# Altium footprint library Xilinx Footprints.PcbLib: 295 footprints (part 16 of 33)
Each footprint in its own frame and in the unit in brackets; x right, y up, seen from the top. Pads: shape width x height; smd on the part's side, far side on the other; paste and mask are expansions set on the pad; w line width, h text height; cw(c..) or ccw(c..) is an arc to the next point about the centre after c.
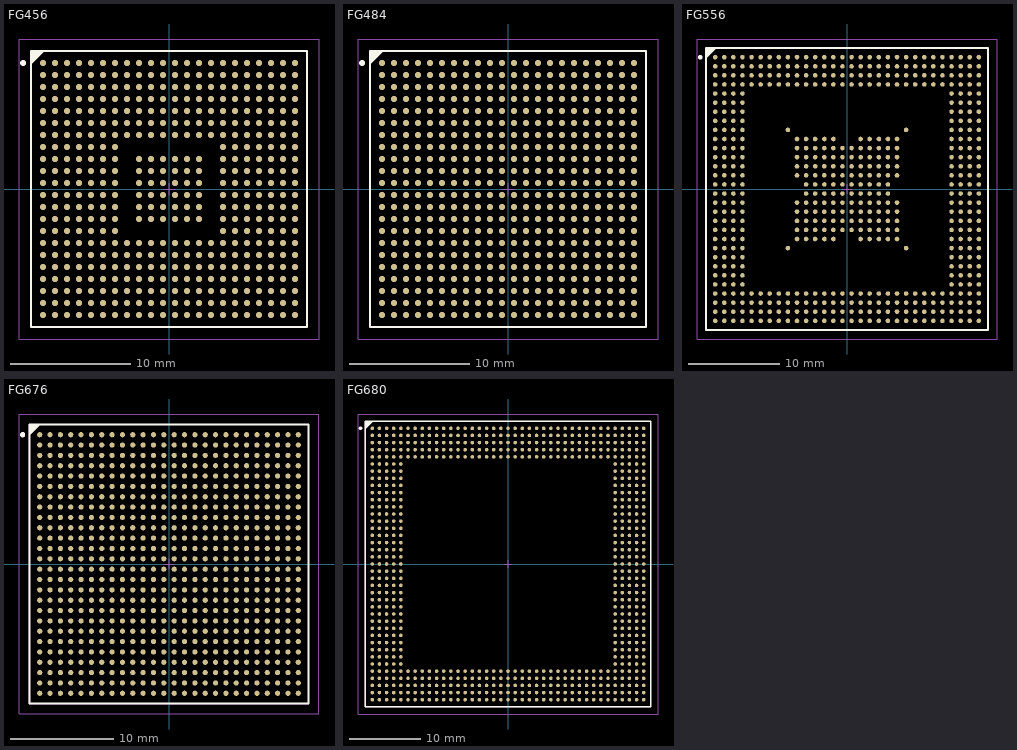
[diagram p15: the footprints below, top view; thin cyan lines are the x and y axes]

## FG456 [mm] "456-Ball Fine Pitch Ball Grid Array (FG456)"
height 2.6
pads (456):
  round 0.5 smd: A1(-10.5,10.5) A2(-9.5,10.5) A3(-8.5,10.5) A4(-7.5,10.5) A5(-6.5,10.5) A6(-5.5,10.5) A7(-4.5,10.5) A8(-3.5,10.5) A9(-2.5,10.5) A10(-1.5,10.5) A11(-0.5,10.5) A12(0.5,10.5) A13(1.5,10.5) A14(2.5,10.5) A15(3.5,10.5) A16(4.5,10.5) A17(5.5,10.5) A18(6.5,10.5) A19(7.5,10.5) A20(8.5,10.5) A21(9.5,10.5) A22(10.5,10.5) AA1(-10.5,-9.5) AA2(-9.5,-9.5) AA3(-8.5,-9.5) AA4(-7.5,-9.5) AA5(-6.5,-9.5) AA6(-5.5,-9.5) AA7(-4.5,-9.5) AA8(-3.5,-9.5) AA9(-2.5,-9.5) AA10(-1.5,-9.5) AA11(-0.5,-9.5) AA12(0.5,-9.5) AA13(1.5,-9.5) AA14(2.5,-9.5) AA15(3.5,-9.5) AA16(4.5,-9.5) AA17(5.5,-9.5) AA18(6.5,-9.5) AA19(7.5,-9.5) AA20(8.5,-9.5) AA21(9.5,-9.5) AA22(10.5,-9.5) AB1(-10.5,-10.5) AB2(-9.5,-10.5) AB3(-8.5,-10.5) AB4(-7.5,-10.5) AB5(-6.5,-10.5) AB6(-5.5,-10.5) AB7(-4.5,-10.5) AB8(-3.5,-10.5) AB9(-2.5,-10.5) AB10(-1.5,-10.5) AB11(-0.5,-10.5) AB12(0.5,-10.5) AB13(1.5,-10.5) AB14(2.5,-10.5) AB15(3.5,-10.5) AB16(4.5,-10.5) AB17(5.5,-10.5) AB18(6.5,-10.5) AB19(7.5,-10.5) AB20(8.5,-10.5) AB21(9.5,-10.5) AB22(10.5,-10.5) B1(-10.5,9.5) B2(-9.5,9.5) B3(-8.5,9.5) B4(-7.5,9.5) B5(-6.5,9.5) B6(-5.5,9.5) B7(-4.5,9.5) B8(-3.5,9.5) B9(-2.5,9.5) B10(-1.5,9.5) B11(-0.5,9.5) B12(0.5,9.5) B13(1.5,9.5) B14(2.5,9.5) B15(3.5,9.5) B16(4.5,9.5) B17(5.5,9.5) B18(6.5,9.5) B19(7.5,9.5) B20(8.5,9.5) B21(9.5,9.5) B22(10.5,9.5) C1(-10.5,8.5) C2(-9.5,8.5) C3(-8.5,8.5) C4(-7.5,8.5) C5(-6.5,8.5) C6(-5.5,8.5) C7(-4.5,8.5) C8(-3.5,8.5) C9(-2.5,8.5) C10(-1.5,8.5) C11(-0.5,8.5) C12(0.5,8.5) C13(1.5,8.5) C14(2.5,8.5) C15(3.5,8.5) C16(4.5,8.5) C17(5.5,8.5) C18(6.5,8.5) C19(7.5,8.5) C20(8.5,8.5) C21(9.5,8.5) C22(10.5,8.5) D1(-10.5,7.5) D2(-9.5,7.5) D3(-8.5,7.5) D4(-7.5,7.5) D5(-6.5,7.5) D6(-5.5,7.5) D7(-4.5,7.5) D8(-3.5,7.5) D9(-2.5,7.5) D10(-1.5,7.5) D11(-0.5,7.5) D12(0.5,7.5) D13(1.5,7.5) D14(2.5,7.5) D15(3.5,7.5) D16(4.5,7.5) D17(5.5,7.5) D18(6.5,7.5) D19(7.5,7.5) D20(8.5,7.5) D21(9.5,7.5) D22(10.5,7.5) E1(-10.5,6.5) E2(-9.5,6.5) E3(-8.5,6.5) E4(-7.5,6.5) E5(-6.5,6.5) E6(-5.5,6.5) E7(-4.5,6.5) E8(-3.5,6.5) E9(-2.5,6.5) E10(-1.5,6.5) E11(-0.5,6.5) E12(0.5,6.5) E13(1.5,6.5) E14(2.5,6.5) E15(3.5,6.5) E16(4.5,6.5) E17(5.5,6.5) E18(6.5,6.5) E19(7.5,6.5) E20(8.5,6.5) E21(9.5,6.5) E22(10.5,6.5) F1(-10.5,5.5) F2(-9.5,5.5) F3(-8.5,5.5) F4(-7.5,5.5) F5(-6.5,5.5) F6(-5.5,5.5) F7(-4.5,5.5) F8(-3.5,5.5) F9(-2.5,5.5) F10(-1.5,5.5) F11(-0.5,5.5) F12(0.5,5.5) F13(1.5,5.5) F14(2.5,5.5) F15(3.5,5.5) F16(4.5,5.5) F17(5.5,5.5) F18(6.5,5.5) F19(7.5,5.5) F20(8.5,5.5) F21(9.5,5.5) F22(10.5,5.5) G1(-10.5,4.5) G2(-9.5,4.5) G3(-8.5,4.5) G4(-7.5,4.5) G5(-6.5,4.5) G6(-5.5,4.5) G7(-4.5,4.5) G8(-3.5,4.5) G9(-2.5,4.5) G10(-1.5,4.5) G11(-0.5,4.5) G12(0.5,4.5) G13(1.5,4.5) G14(2.5,4.5) G15(3.5,4.5) G16(4.5,4.5) G17(5.5,4.5) G18(6.5,4.5) G19(7.5,4.5) G20(8.5,4.5) G21(9.5,4.5) G22(10.5,4.5) H1(-10.5,3.5) H2(-9.5,3.5) H3(-8.5,3.5) H4(-7.5,3.5) H5(-6.5,3.5) H6(-5.5,3.5) H7(-4.5,3.5) H16(4.5,3.5) H17(5.5,3.5) H18(6.5,3.5) H19(7.5,3.5) H20(8.5,3.5) H21(9.5,3.5) H22(10.5,3.5) J1(-10.5,2.5) J2(-9.5,2.5) J3(-8.5,2.5) J4(-7.5,2.5) J5(-6.5,2.5) J6(-5.5,2.5) J7(-4.5,2.5) J9(-2.5,2.5) J10(-1.5,2.5) J11(-0.5,2.5) J12(0.5,2.5) J13(1.5,2.5) J14(2.5,2.5) J16(4.5,2.5) J17(5.5,2.5) J18(6.5,2.5) J19(7.5,2.5) J20(8.5,2.5) J21(9.5,2.5) J22(10.5,2.5) K1(-10.5,1.5) K2(-9.5,1.5) K3(-8.5,1.5) K4(-7.5,1.5) K5(-6.5,1.5) K6(-5.5,1.5) K7(-4.5,1.5) K9(-2.5,1.5) K10(-1.5,1.5) K11(-0.5,1.5) K12(0.5,1.5) K13(1.5,1.5) K14(2.5,1.5) K16(4.5,1.5) K17(5.5,1.5) K18(6.5,1.5) K19(7.5,1.5) K20(8.5,1.5) K21(9.5,1.5) K22(10.5,1.5) L1(-10.5,0.5) L2(-9.5,0.5) L3(-8.5,0.5) L4(-7.5,0.5) L5(-6.5,0.5) L6(-5.5,0.5) L7(-4.5,0.5) L9(-2.5,0.5) L10(-1.5,0.5) L11(-0.5,0.5) L12(0.5,0.5) L13(1.5,0.5) L14(2.5,0.5) L16(4.5,0.5) L17(5.5,0.5) L18(6.5,0.5) L19(7.5,0.5) L20(8.5,0.5) L21(9.5,0.5) L22(10.5,0.5) M1(-10.5,-0.5) M2(-9.5,-0.5) M3(-8.5,-0.5) M4(-7.5,-0.5) M5(-6.5,-0.5) M6(-5.5,-0.5) M7(-4.5,-0.5) M9(-2.5,-0.5) M10(-1.5,-0.5) M11(-0.5,-0.5) M12(0.5,-0.5) M13(1.5,-0.5) M14(2.5,-0.5) M16(4.5,-0.5) M17(5.5,-0.5) M18(6.5,-0.5) M19(7.5,-0.5) M20(8.5,-0.5) M21(9.5,-0.5) M22(10.5,-0.5) N1(-10.5,-1.5) N2(-9.5,-1.5) N3(-8.5,-1.5) N4(-7.5,-1.5) N5(-6.5,-1.5) N6(-5.5,-1.5) N7(-4.5,-1.5) N9(-2.5,-1.5) N10(-1.5,-1.5) N11(-0.5,-1.5) N12(0.5,-1.5) N13(1.5,-1.5) N14(2.5,-1.5) N16(4.5,-1.5) N17(5.5,-1.5) N18(6.5,-1.5) N19(7.5,-1.5) N20(8.5,-1.5) N21(9.5,-1.5) N22(10.5,-1.5) P1(-10.5,-2.5) P2(-9.5,-2.5) P3(-8.5,-2.5) P4(-7.5,-2.5) P5(-6.5,-2.5) P6(-5.5,-2.5) P7(-4.5,-2.5) P9(-2.5,-2.5) P10(-1.5,-2.5) P11(-0.5,-2.5) P12(0.5,-2.5) P13(1.5,-2.5) P14(2.5,-2.5) P16(4.5,-2.5) P17(5.5,-2.5) P18(6.5,-2.5) P19(7.5,-2.5) P20(8.5,-2.5) P21(9.5,-2.5) P22(10.5,-2.5) R1(-10.5,-3.5) R2(-9.5,-3.5) R3(-8.5,-3.5) R4(-7.5,-3.5) R5(-6.5,-3.5) R6(-5.5,-3.5) R7(-4.5,-3.5) R16(4.5,-3.5) R17(5.5,-3.5) R18(6.5,-3.5) R19(7.5,-3.5) R20(8.5,-3.5) R21(9.5,-3.5) R22(10.5,-3.5) T1(-10.5,-4.5) T2(-9.5,-4.5) T3(-8.5,-4.5) T4(-7.5,-4.5) T5(-6.5,-4.5) T6(-5.5,-4.5) T7(-4.5,-4.5) T8(-3.5,-4.5) T9(-2.5,-4.5) T10(-1.5,-4.5) T11(-0.5,-4.5) T12(0.5,-4.5) T13(1.5,-4.5) T14(2.5,-4.5) T15(3.5,-4.5) T16(4.5,-4.5) T17(5.5,-4.5) T18(6.5,-4.5) T19(7.5,-4.5) T20(8.5,-4.5) T21(9.5,-4.5) T22(10.5,-4.5) U1(-10.5,-5.5) U2(-9.5,-5.5) U3(-8.5,-5.5) U4(-7.5,-5.5) U5(-6.5,-5.5) U6(-5.5,-5.5) U7(-4.5,-5.5) U8(-3.5,-5.5) U9(-2.5,-5.5) U10(-1.5,-5.5) U11(-0.5,-5.5) U12(0.5,-5.5) U13(1.5,-5.5) U14(2.5,-5.5) U15(3.5,-5.5) U16(4.5,-5.5) U17(5.5,-5.5) U18(6.5,-5.5) U19(7.5,-5.5) U20(8.5,-5.5) U21(9.5,-5.5) U22(10.5,-5.5) V1(-10.5,-6.5) V2(-9.5,-6.5) V3(-8.5,-6.5) V4(-7.5,-6.5) V5(-6.5,-6.5) V6(-5.5,-6.5) V7(-4.5,-6.5) V8(-3.5,-6.5) V9(-2.5,-6.5) V10(-1.5,-6.5) V11(-0.5,-6.5) V12(0.5,-6.5) V13(1.5,-6.5) V14(2.5,-6.5) V15(3.5,-6.5) V16(4.5,-6.5) V17(5.5,-6.5) V18(6.5,-6.5) V19(7.5,-6.5) V20(8.5,-6.5) V21(9.5,-6.5) V22(10.5,-6.5) W1(-10.5,-7.5) W2(-9.5,-7.5) W3(-8.5,-7.5) W4(-7.5,-7.5) W5(-6.5,-7.5) W6(-5.5,-7.5) W7(-4.5,-7.5) W8(-3.5,-7.5) W9(-2.5,-7.5) W10(-1.5,-7.5) W11(-0.5,-7.5) W12(0.5,-7.5) W13(1.5,-7.5) W14(2.5,-7.5) W15(3.5,-7.5) W16(4.5,-7.5) W17(5.5,-7.5) W18(6.5,-7.5) W19(7.5,-7.5) W20(8.5,-7.5) W21(9.5,-7.5) W22(10.5,-7.5) Y1(-10.5,-8.5) Y2(-9.5,-8.5) Y3(-8.5,-8.5) Y4(-7.5,-8.5) Y5(-6.5,-8.5) Y6(-5.5,-8.5) Y7(-4.5,-8.5) Y8(-3.5,-8.5) Y9(-2.5,-8.5) Y10(-1.5,-8.5) Y11(-0.5,-8.5) Y12(0.5,-8.5) Y13(1.5,-8.5) Y14(2.5,-8.5) Y15(3.5,-8.5) Y16(4.5,-8.5) Y17(5.5,-8.5) Y18(6.5,-8.5) Y19(7.5,-8.5) Y20(8.5,-8.5) Y21(9.5,-8.5) Y22(10.5,-8.5)
Top Overlay:
  circle w0.25: c-12.15,10.5 r0.125
  region: -10.5,11.5 -11.5,10.5 -11.5,11.5
  lines w0.2: -11.5,10.5 -10.5,11.5 ; -11.5,-11.5 -11.5,11.5 11.5,11.5 11.5,-11.5 -11.5,-11.5
Mechanical 13:
  lines w0.1: -11.5,-11.5 -11.5,11.5 11.5,11.5 11.5,-11.5 -11.5,-11.5
Mechanical 15:
  lines w0.1: -0.5,0 0.5,0 ; 0,-0.5 0,0.5 ; -12.5,-12.5 -12.5,12.5 12.5,12.5 12.5,-12.5 -12.5,-12.5
3D body: height 2.6, standoff 0, extent -11.5,-11.5 11.5,11.5

## FG484 [mm] "484-Ball Fine Pitch Ball Grid Array 1.00 mm Pitch (FG484)"
height 2.6
pads (484):
  round 0.5 smd: A1(-10.5,10.5) A2(-9.5,10.5) A3(-8.5,10.5) A4(-7.5,10.5) A5(-6.5,10.5) A6(-5.5,10.5) A7(-4.5,10.5) A8(-3.5,10.5) A9(-2.5,10.5) A10(-1.5,10.5) A11(-0.5,10.5) A12(0.5,10.5) A13(1.5,10.5) A14(2.5,10.5) A15(3.5,10.5) A16(4.5,10.5) A17(5.5,10.5) A18(6.5,10.5) A19(7.5,10.5) A20(8.5,10.5) A21(9.5,10.5) A22(10.5,10.5) AA1(-10.5,-9.5) AA2(-9.5,-9.5) AA3(-8.5,-9.5) AA4(-7.5,-9.5) AA5(-6.5,-9.5) AA6(-5.5,-9.5) AA7(-4.5,-9.5) AA8(-3.5,-9.5) AA9(-2.5,-9.5) AA10(-1.5,-9.5) AA11(-0.5,-9.5) AA12(0.5,-9.5) AA13(1.5,-9.5) AA14(2.5,-9.5) AA15(3.5,-9.5) AA16(4.5,-9.5) AA17(5.5,-9.5) AA18(6.5,-9.5) AA19(7.5,-9.5) AA20(8.5,-9.5) AA21(9.5,-9.5) AA22(10.5,-9.5) AB1(-10.5,-10.5) AB2(-9.5,-10.5) AB3(-8.5,-10.5) AB4(-7.5,-10.5) AB5(-6.5,-10.5) AB6(-5.5,-10.5) AB7(-4.5,-10.5) AB8(-3.5,-10.5) AB9(-2.5,-10.5) AB10(-1.5,-10.5) AB11(-0.5,-10.5) AB12(0.5,-10.5) AB13(1.5,-10.5) AB14(2.5,-10.5) AB15(3.5,-10.5) AB16(4.5,-10.5) AB17(5.5,-10.5) AB18(6.5,-10.5) AB19(7.5,-10.5) AB20(8.5,-10.5) AB21(9.5,-10.5) AB22(10.5,-10.5) B1(-10.5,9.5) B2(-9.5,9.5) B3(-8.5,9.5) B4(-7.5,9.5) B5(-6.5,9.5) B6(-5.5,9.5) B7(-4.5,9.5) B8(-3.5,9.5) B9(-2.5,9.5) B10(-1.5,9.5) B11(-0.5,9.5) B12(0.5,9.5) B13(1.5,9.5) B14(2.5,9.5) B15(3.5,9.5) B16(4.5,9.5) B17(5.5,9.5) B18(6.5,9.5) B19(7.5,9.5) B20(8.5,9.5) B21(9.5,9.5) B22(10.5,9.5) C1(-10.5,8.5) C2(-9.5,8.5) C3(-8.5,8.5) C4(-7.5,8.5) C5(-6.5,8.5) C6(-5.5,8.5) C7(-4.5,8.5) C8(-3.5,8.5) C9(-2.5,8.5) C10(-1.5,8.5) C11(-0.5,8.5) C12(0.5,8.5) C13(1.5,8.5) C14(2.5,8.5) C15(3.5,8.5) C16(4.5,8.5) C17(5.5,8.5) C18(6.5,8.5) C19(7.5,8.5) C20(8.5,8.5) C21(9.5,8.5) C22(10.5,8.5) D1(-10.5,7.5) D2(-9.5,7.5) D3(-8.5,7.5) D4(-7.5,7.5) D5(-6.5,7.5) D6(-5.5,7.5) D7(-4.5,7.5) D8(-3.5,7.5) D9(-2.5,7.5) D10(-1.5,7.5) D11(-0.5,7.5) D12(0.5,7.5) D13(1.5,7.5) D14(2.5,7.5) D15(3.5,7.5) D16(4.5,7.5) D17(5.5,7.5) D18(6.5,7.5) D19(7.5,7.5) D20(8.5,7.5) D21(9.5,7.5) D22(10.5,7.5) E1(-10.5,6.5) E2(-9.5,6.5) E3(-8.5,6.5) E4(-7.5,6.5) E5(-6.5,6.5) E6(-5.5,6.5) E7(-4.5,6.5) E8(-3.5,6.5) E9(-2.5,6.5) E10(-1.5,6.5) E11(-0.5,6.5) E12(0.5,6.5) E13(1.5,6.5) E14(2.5,6.5) E15(3.5,6.5) E16(4.5,6.5) E17(5.5,6.5) E18(6.5,6.5) E19(7.5,6.5) E20(8.5,6.5) E21(9.5,6.5) E22(10.5,6.5) F1(-10.5,5.5) F2(-9.5,5.5) F3(-8.5,5.5) F4(-7.5,5.5) F5(-6.5,5.5) F6(-5.5,5.5) F7(-4.5,5.5) F8(-3.5,5.5) F9(-2.5,5.5) F10(-1.5,5.5) F11(-0.5,5.5) F12(0.5,5.5) F13(1.5,5.5) F14(2.5,5.5) F15(3.5,5.5) F16(4.5,5.5) F17(5.5,5.5) F18(6.5,5.5) F19(7.5,5.5) F20(8.5,5.5) F21(9.5,5.5) F22(10.5,5.5) G1(-10.5,4.5) G2(-9.5,4.5) G3(-8.5,4.5) G4(-7.5,4.5) G5(-6.5,4.5) G6(-5.5,4.5) G7(-4.5,4.5) G8(-3.5,4.5) G9(-2.5,4.5) G10(-1.5,4.5) G11(-0.5,4.5) G12(0.5,4.5) G13(1.5,4.5) G14(2.5,4.5) G15(3.5,4.5) G16(4.5,4.5) G17(5.5,4.5) G18(6.5,4.5) G19(7.5,4.5) G20(8.5,4.5) G21(9.5,4.5) G22(10.5,4.5) H1(-10.5,3.5) H2(-9.5,3.5) H3(-8.5,3.5) H4(-7.5,3.5) H5(-6.5,3.5) H6(-5.5,3.5) H7(-4.5,3.5) H8(-3.5,3.5) H9(-2.5,3.5) H10(-1.5,3.5) H11(-0.5,3.5) H12(0.5,3.5) H13(1.5,3.5) H14(2.5,3.5) H15(3.5,3.5) H16(4.5,3.5) H17(5.5,3.5) H18(6.5,3.5) H19(7.5,3.5) H20(8.5,3.5) H21(9.5,3.5) H22(10.5,3.5) J1(-10.5,2.5) J2(-9.5,2.5) J3(-8.5,2.5) J4(-7.5,2.5) J5(-6.5,2.5) J6(-5.5,2.5) J7(-4.5,2.5) J8(-3.5,2.5) J9(-2.5,2.5) J10(-1.5,2.5) J11(-0.5,2.5) J12(0.5,2.5) J13(1.5,2.5) J14(2.5,2.5) J15(3.5,2.5) J16(4.5,2.5) J17(5.5,2.5) J18(6.5,2.5) J19(7.5,2.5) J20(8.5,2.5) J21(9.5,2.5) J22(10.5,2.5) K1(-10.5,1.5) K2(-9.5,1.5) K3(-8.5,1.5) K4(-7.5,1.5) K5(-6.5,1.5) K6(-5.5,1.5) K7(-4.5,1.5) K8(-3.5,1.5) K9(-2.5,1.5) K10(-1.5,1.5) K11(-0.5,1.5) K12(0.5,1.5) K13(1.5,1.5) K14(2.5,1.5) K15(3.5,1.5) K16(4.5,1.5) K17(5.5,1.5) K18(6.5,1.5) K19(7.5,1.5) K20(8.5,1.5) K21(9.5,1.5) K22(10.5,1.5) L1(-10.5,0.5) L2(-9.5,0.5) L3(-8.5,0.5) L4(-7.5,0.5) L5(-6.5,0.5) L6(-5.5,0.5) L7(-4.5,0.5) L8(-3.5,0.5) L9(-2.5,0.5) L10(-1.5,0.5) L11(-0.5,0.5) L12(0.5,0.5) L13(1.5,0.5) L14(2.5,0.5) L15(3.5,0.5) L16(4.5,0.5) L17(5.5,0.5) L18(6.5,0.5) L19(7.5,0.5) L20(8.5,0.5) L21(9.5,0.5) L22(10.5,0.5) M1(-10.5,-0.5) M2(-9.5,-0.5) M3(-8.5,-0.5) M4(-7.5,-0.5) M5(-6.5,-0.5) M6(-5.5,-0.5) M7(-4.5,-0.5) M8(-3.5,-0.5) M9(-2.5,-0.5) M10(-1.5,-0.5) M11(-0.5,-0.5) M12(0.5,-0.5) M13(1.5,-0.5) M14(2.5,-0.5) M15(3.5,-0.5) M16(4.5,-0.5) M17(5.5,-0.5) M18(6.5,-0.5) M19(7.5,-0.5) M20(8.5,-0.5) M21(9.5,-0.5) M22(10.5,-0.5) N1(-10.5,-1.5) N2(-9.5,-1.5) N3(-8.5,-1.5) N4(-7.5,-1.5) N5(-6.5,-1.5) N6(-5.5,-1.5) N7(-4.5,-1.5) N8(-3.5,-1.5) N9(-2.5,-1.5) N10(-1.5,-1.5) N11(-0.5,-1.5) N12(0.5,-1.5) N13(1.5,-1.5) N14(2.5,-1.5) N15(3.5,-1.5) N16(4.5,-1.5) N17(5.5,-1.5) N18(6.5,-1.5) N19(7.5,-1.5) N20(8.5,-1.5) N21(9.5,-1.5) N22(10.5,-1.5) P1(-10.5,-2.5) P2(-9.5,-2.5) P3(-8.5,-2.5) P4(-7.5,-2.5) P5(-6.5,-2.5) P6(-5.5,-2.5) P7(-4.5,-2.5) P8(-3.5,-2.5) P9(-2.5,-2.5) P10(-1.5,-2.5) P11(-0.5,-2.5) P12(0.5,-2.5) P13(1.5,-2.5) P14(2.5,-2.5) P15(3.5,-2.5) P16(4.5,-2.5) P17(5.5,-2.5) P18(6.5,-2.5) P19(7.5,-2.5) P20(8.5,-2.5) P21(9.5,-2.5) P22(10.5,-2.5) R1(-10.5,-3.5) R2(-9.5,-3.5) R3(-8.5,-3.5) R4(-7.5,-3.5) R5(-6.5,-3.5) R6(-5.5,-3.5) R7(-4.5,-3.5) R8(-3.5,-3.5) R9(-2.5,-3.5) R10(-1.5,-3.5) R11(-0.5,-3.5) R12(0.5,-3.5) R13(1.5,-3.5) R14(2.5,-3.5) R15(3.5,-3.5) R16(4.5,-3.5) R17(5.5,-3.5) R18(6.5,-3.5) R19(7.5,-3.5) R20(8.5,-3.5) R21(9.5,-3.5) R22(10.5,-3.5) T1(-10.5,-4.5) T2(-9.5,-4.5) T3(-8.5,-4.5) T4(-7.5,-4.5) T5(-6.5,-4.5) T6(-5.5,-4.5) T7(-4.5,-4.5) T8(-3.5,-4.5) T9(-2.5,-4.5) T10(-1.5,-4.5) T11(-0.5,-4.5) T12(0.5,-4.5) T13(1.5,-4.5) T14(2.5,-4.5) T15(3.5,-4.5) T16(4.5,-4.5) T17(5.5,-4.5) T18(6.5,-4.5) T19(7.5,-4.5) T20(8.5,-4.5) T21(9.5,-4.5) T22(10.5,-4.5) U1(-10.5,-5.5) U2(-9.5,-5.5) U3(-8.5,-5.5) U4(-7.5,-5.5) U5(-6.5,-5.5) U6(-5.5,-5.5) U7(-4.5,-5.5) U8(-3.5,-5.5) U9(-2.5,-5.5) U10(-1.5,-5.5) U11(-0.5,-5.5) U12(0.5,-5.5) U13(1.5,-5.5) U14(2.5,-5.5) U15(3.5,-5.5) U16(4.5,-5.5) U17(5.5,-5.5) U18(6.5,-5.5) U19(7.5,-5.5) U20(8.5,-5.5) U21(9.5,-5.5) U22(10.5,-5.5) V1(-10.5,-6.5) V2(-9.5,-6.5) V3(-8.5,-6.5) V4(-7.5,-6.5) V5(-6.5,-6.5) V6(-5.5,-6.5) V7(-4.5,-6.5) V8(-3.5,-6.5) V9(-2.5,-6.5) V10(-1.5,-6.5) V11(-0.5,-6.5) V12(0.5,-6.5) V13(1.5,-6.5) V14(2.5,-6.5) V15(3.5,-6.5) V16(4.5,-6.5) V17(5.5,-6.5) V18(6.5,-6.5) V19(7.5,-6.5) V20(8.5,-6.5) V21(9.5,-6.5) V22(10.5,-6.5) W1(-10.5,-7.5) W2(-9.5,-7.5) W3(-8.5,-7.5) W4(-7.5,-7.5) W5(-6.5,-7.5) W6(-5.5,-7.5) W7(-4.5,-7.5) W8(-3.5,-7.5) W9(-2.5,-7.5) W10(-1.5,-7.5) W11(-0.5,-7.5) W12(0.5,-7.5) W13(1.5,-7.5) W14(2.5,-7.5) W15(3.5,-7.5) W16(4.5,-7.5) W17(5.5,-7.5) W18(6.5,-7.5) W19(7.5,-7.5) W20(8.5,-7.5) W21(9.5,-7.5) W22(10.5,-7.5) Y1(-10.5,-8.5) Y2(-9.5,-8.5) Y3(-8.5,-8.5) Y4(-7.5,-8.5) Y5(-6.5,-8.5) Y6(-5.5,-8.5) Y7(-4.5,-8.5) Y8(-3.5,-8.5) Y9(-2.5,-8.5) Y10(-1.5,-8.5) Y11(-0.5,-8.5) Y12(0.5,-8.5) Y13(1.5,-8.5) Y14(2.5,-8.5) Y15(3.5,-8.5) Y16(4.5,-8.5) Y17(5.5,-8.5) Y18(6.5,-8.5) Y19(7.5,-8.5) Y20(8.5,-8.5) Y21(9.5,-8.5) Y22(10.5,-8.5)
Top Overlay:
  circle w0.25: c-12.15,10.5 r0.125
  region: -10.5,11.5 -11.5,10.5 -11.5,11.5
  lines w0.2: -11.5,10.5 -10.5,11.5 ; -11.5,-11.5 -11.5,11.5 11.5,11.5 11.5,-11.5 -11.5,-11.5
Mechanical 13:
  lines w0.1: -11.5,-11.5 -11.5,11.5 11.5,11.5 11.5,-11.5 -11.5,-11.5
Mechanical 15:
  lines w0.1: -0.5,0 0.5,0 ; 0,-0.5 0,0.5 ; -12.5,-12.5 -12.5,12.5 12.5,12.5 12.5,-12.5 -12.5,-12.5
3D body: height 2.6, standoff 0, extent -11.5,-11.5 11.5,11.5

## FG556 [mm] "556-Ball Fine Pitch Ball Grid Array 1.00 mm Pitch (FG556)"
height 2.6
pads (556):
  round 0.5 smd: A1(-14.5,14.5) A2(-13.5,14.5) A3(-12.5,14.5) A4(-11.5,14.5) A5(-10.5,14.5) A6(-9.5,14.5) A7(-8.5,14.5) A8(-7.5,14.5) A9(-6.5,14.5) A10(-5.5,14.5) A11(-4.5,14.5) A12(-3.5,14.5) A13(-2.5,14.5) A14(-1.5,14.5) A15(-0.5,14.5) A16(0.5,14.5) A17(1.5,14.5) A18(2.5,14.5) A19(3.5,14.5) A20(4.5,14.5) A21(5.5,14.5) A22(6.5,14.5) A23(7.5,14.5) A24(8.5,14.5) A25(9.5,14.5) A26(10.5,14.5) A27(11.5,14.5) A28(12.5,14.5) A29(13.5,14.5) A30(14.5,14.5) AA1(-14.5,-5.5) AA2(-13.5,-5.5) AA3(-12.5,-5.5) AA4(-11.5,-5.5) AA10(-5.5,-5.5) AA11(-4.5,-5.5) AA12(-3.5,-5.5) AA13(-2.5,-5.5) AA14(-1.5,-5.5) AA17(1.5,-5.5) AA18(2.5,-5.5) AA19(3.5,-5.5) AA20(4.5,-5.5) AA21(5.5,-5.5) AA27(11.5,-5.5) AA28(12.5,-5.5) AA29(13.5,-5.5) AA30(14.5,-5.5) AB1(-14.5,-6.5) AB2(-13.5,-6.5) AB3(-12.5,-6.5) AB4(-11.5,-6.5) AB9(-6.5,-6.5) AB22(6.5,-6.5) AB27(11.5,-6.5) AB28(12.5,-6.5) AB29(13.5,-6.5) AB30(14.5,-6.5) AC1(-14.5,-7.5) AC2(-13.5,-7.5) AC3(-12.5,-7.5) AC4(-11.5,-7.5) AC27(11.5,-7.5) AC28(12.5,-7.5) AC29(13.5,-7.5) AC30(14.5,-7.5) AD1(-14.5,-8.5) AD2(-13.5,-8.5) AD3(-12.5,-8.5) AD4(-11.5,-8.5) AD27(11.5,-8.5) AD28(12.5,-8.5) AD29(13.5,-8.5) AD30(14.5,-8.5) AE1(-14.5,-9.5) AE2(-13.5,-9.5) AE3(-12.5,-9.5) AE4(-11.5,-9.5) AE27(11.5,-9.5) AE28(12.5,-9.5) AE29(13.5,-9.5) AE30(14.5,-9.5) AF1(-14.5,-10.5) AF2(-13.5,-10.5) AF3(-12.5,-10.5) AF4(-11.5,-10.5) AF27(11.5,-10.5) AF28(12.5,-10.5) AF29(13.5,-10.5) AF30(14.5,-10.5) AG1(-14.5,-11.5) AG2(-13.5,-11.5) AG3(-12.5,-11.5) AG4(-11.5,-11.5) AG5(-10.5,-11.5) AG6(-9.5,-11.5) AG7(-8.5,-11.5) AG8(-7.5,-11.5) AG9(-6.5,-11.5) AG10(-5.5,-11.5) AG11(-4.5,-11.5) AG12(-3.5,-11.5) AG13(-2.5,-11.5) AG14(-1.5,-11.5) AG15(-0.5,-11.5) AG16(0.5,-11.5) AG17(1.5,-11.5) AG18(2.5,-11.5) AG19(3.5,-11.5) AG20(4.5,-11.5) AG21(5.5,-11.5) AG22(6.5,-11.5) AG23(7.5,-11.5) AG24(8.5,-11.5) AG25(9.5,-11.5) AG26(10.5,-11.5) AG27(11.5,-11.5) AG28(12.5,-11.5) AG29(13.5,-11.5) AG30(14.5,-11.5) AH1(-14.5,-12.5) AH2(-13.5,-12.5) AH3(-12.5,-12.5) AH4(-11.5,-12.5) AH5(-10.5,-12.5) AH6(-9.5,-12.5) AH7(-8.5,-12.5) AH8(-7.5,-12.5) AH9(-6.5,-12.5) AH10(-5.5,-12.5) AH11(-4.5,-12.5) AH12(-3.5,-12.5) AH13(-2.5,-12.5) AH14(-1.5,-12.5) AH15(-0.5,-12.5) AH16(0.5,-12.5) AH17(1.5,-12.5) AH18(2.5,-12.5) AH19(3.5,-12.5) AH20(4.5,-12.5) AH21(5.5,-12.5) AH22(6.5,-12.5) AH23(7.5,-12.5) AH24(8.5,-12.5) AH25(9.5,-12.5) AH26(10.5,-12.5) AH27(11.5,-12.5) AH28(12.5,-12.5) AH29(13.5,-12.5) AH30(14.5,-12.5) AJ1(-14.5,-13.5) AJ2(-13.5,-13.5) AJ3(-12.5,-13.5) AJ4(-11.5,-13.5) AJ5(-10.5,-13.5) AJ6(-9.5,-13.5) AJ7(-8.5,-13.5) AJ8(-7.5,-13.5) AJ9(-6.5,-13.5) AJ10(-5.5,-13.5) AJ11(-4.5,-13.5) AJ12(-3.5,-13.5) AJ13(-2.5,-13.5) AJ14(-1.5,-13.5) AJ15(-0.5,-13.5) AJ16(0.5,-13.5) AJ17(1.5,-13.5) AJ18(2.5,-13.5) AJ19(3.5,-13.5) AJ20(4.5,-13.5) AJ21(5.5,-13.5) AJ22(6.5,-13.5) AJ23(7.5,-13.5) AJ24(8.5,-13.5) AJ25(9.5,-13.5) AJ26(10.5,-13.5) AJ27(11.5,-13.5) AJ28(12.5,-13.5) AJ29(13.5,-13.5) AJ30(14.5,-13.5) AK1(-14.5,-14.5) AK2(-13.5,-14.5) AK3(-12.5,-14.5) AK4(-11.5,-14.5) AK5(-10.5,-14.5) AK6(-9.5,-14.5) AK7(-8.5,-14.5) AK8(-7.5,-14.5) AK9(-6.5,-14.5) AK10(-5.5,-14.5) AK11(-4.5,-14.5) AK12(-3.5,-14.5) AK13(-2.5,-14.5) AK14(-1.5,-14.5) AK15(-0.5,-14.5) AK16(0.5,-14.5) AK17(1.5,-14.5) AK18(2.5,-14.5) AK19(3.5,-14.5) AK20(4.5,-14.5) AK21(5.5,-14.5) AK22(6.5,-14.5) AK23(7.5,-14.5) AK24(8.5,-14.5) AK25(9.5,-14.5) AK26(10.5,-14.5) AK27(11.5,-14.5) AK28(12.5,-14.5) AK29(13.5,-14.5) AK30(14.5,-14.5) B1(-14.5,13.5) B2(-13.5,13.5) B3(-12.5,13.5) B4(-11.5,13.5) B5(-10.5,13.5) B6(-9.5,13.5) B7(-8.5,13.5) B8(-7.5,13.5) B9(-6.5,13.5) B10(-5.5,13.5) B11(-4.5,13.5) B12(-3.5,13.5) B13(-2.5,13.5) B14(-1.5,13.5) B15(-0.5,13.5) B16(0.5,13.5) B17(1.5,13.5) B18(2.5,13.5) B19(3.5,13.5) B20(4.5,13.5) B21(5.5,13.5) B22(6.5,13.5) B23(7.5,13.5) B24(8.5,13.5) B25(9.5,13.5) B26(10.5,13.5) B27(11.5,13.5) B28(12.5,13.5) B29(13.5,13.5) B30(14.5,13.5) C1(-14.5,12.5) C2(-13.5,12.5) C3(-12.5,12.5) C4(-11.5,12.5) C5(-10.5,12.5) C6(-9.5,12.5) C7(-8.5,12.5) C8(-7.5,12.5) C9(-6.5,12.5) C10(-5.5,12.5) C11(-4.5,12.5) C12(-3.5,12.5) C13(-2.5,12.5) C14(-1.5,12.5) C15(-0.5,12.5) C16(0.5,12.5) C17(1.5,12.5) C18(2.5,12.5) C19(3.5,12.5) C20(4.5,12.5) C21(5.5,12.5) C22(6.5,12.5) C23(7.5,12.5) C24(8.5,12.5) C25(9.5,12.5) C26(10.5,12.5) C27(11.5,12.5) C28(12.5,12.5) C29(13.5,12.5) C30(14.5,12.5) D1(-14.5,11.5) D2(-13.5,11.5) D3(-12.5,11.5) D4(-11.5,11.5) D5(-10.5,11.5) D6(-9.5,11.5) D7(-8.5,11.5) D8(-7.5,11.5) D9(-6.5,11.5) D10(-5.5,11.5) D11(-4.5,11.5) D12(-3.5,11.5) D13(-2.5,11.5) D14(-1.5,11.5) D15(-0.5,11.5) D16(0.5,11.5) D17(1.5,11.5) D18(2.5,11.5) D19(3.5,11.5) D20(4.5,11.5) D21(5.5,11.5) D22(6.5,11.5) D23(7.5,11.5) D24(8.5,11.5) D25(9.5,11.5) D26(10.5,11.5) D27(11.5,11.5) D28(12.5,11.5) D29(13.5,11.5) D30(14.5,11.5) E1(-14.5,10.5) E2(-13.5,10.5) E3(-12.5,10.5) E4(-11.5,10.5) E27(11.5,10.5) E28(12.5,10.5) E29(13.5,10.5) E30(14.5,10.5) F1(-14.5,9.5) F2(-13.5,9.5) F3(-12.5,9.5) F4(-11.5,9.5) F27(11.5,9.5) F28(12.5,9.5) F29(13.5,9.5) F30(14.5,9.5) G1(-14.5,8.5) G2(-13.5,8.5) G3(-12.5,8.5) G4(-11.5,8.5) G27(11.5,8.5) G28(12.5,8.5) G29(13.5,8.5) G30(14.5,8.5) H1(-14.5,7.5) H2(-13.5,7.5) H3(-12.5,7.5) H4(-11.5,7.5) H27(11.5,7.5) H28(12.5,7.5) H29(13.5,7.5) H30(14.5,7.5) J1(-14.5,6.5) J2(-13.5,6.5) J3(-12.5,6.5) J4(-11.5,6.5) J9(-6.5,6.5) J22(6.5,6.5) J27(11.5,6.5) J28(12.5,6.5) J29(13.5,6.5) J30(14.5,6.5) K1(-14.5,5.5) K2(-13.5,5.5) K3(-12.5,5.5) K4(-11.5,5.5) K10(-5.5,5.5) K11(-4.5,5.5) K12(-3.5,5.5) K13(-2.5,5.5) K14(-1.5,5.5) K17(1.5,5.5) K18(2.5,5.5) K19(3.5,5.5) K20(4.5,5.5) K21(5.5,5.5) K27(11.5,5.5) K28(12.5,5.5) K29(13.5,5.5) K30(14.5,5.5) L1(-14.5,4.5) L2(-13.5,4.5) L3(-12.5,4.5) L4(-11.5,4.5) L10(-5.5,4.5) L11(-4.5,4.5) L12(-3.5,4.5) L13(-2.5,4.5) L14(-1.5,4.5) L15(-0.5,4.5) L16(0.5,4.5) L17(1.5,4.5) L18(2.5,4.5) L19(3.5,4.5) L20(4.5,4.5) L21(5.5,4.5) L27(11.5,4.5) L28(12.5,4.5) L29(13.5,4.5) L30(14.5,4.5) M1(-14.5,3.5) M2(-13.5,3.5) M3(-12.5,3.5) M4(-11.5,3.5) M10(-5.5,3.5) M11(-4.5,3.5) M12(-3.5,3.5) M13(-2.5,3.5) M14(-1.5,3.5) M15(-0.5,3.5) M16(0.5,3.5) M17(1.5,3.5) M18(2.5,3.5) M19(3.5,3.5) M20(4.5,3.5) M21(5.5,3.5) M27(11.5,3.5) M28(12.5,3.5) M29(13.5,3.5) M30(14.5,3.5) N1(-14.5,2.5) N2(-13.5,2.5) N3(-12.5,2.5) N4(-11.5,2.5) N10(-5.5,2.5) N11(-4.5,2.5) N12(-3.5,2.5) N13(-2.5,2.5) N14(-1.5,2.5) N15(-0.5,2.5) N16(0.5,2.5) N17(1.5,2.5) N18(2.5,2.5) N19(3.5,2.5) N20(4.5,2.5) N21(5.5,2.5) N27(11.5,2.5) N28(12.5,2.5) N29(13.5,2.5) N30(14.5,2.5) P1(-14.5,1.5) P2(-13.5,1.5) P3(-12.5,1.5) P4(-11.5,1.5) P10(-5.5,1.5) P11(-4.5,1.5) P12(-3.5,1.5) P13(-2.5,1.5) P14(-1.5,1.5) P15(-0.5,1.5) P16(0.5,1.5) P17(1.5,1.5) P18(2.5,1.5) P19(3.5,1.5) P20(4.5,1.5) P21(5.5,1.5) P27(11.5,1.5) P28(12.5,1.5) P29(13.5,1.5) P30(14.5,1.5) R1(-14.5,0.5) R2(-13.5,0.5) R3(-12.5,0.5) R4(-11.5,0.5) R11(-4.5,0.5) R12(-3.5,0.5) R13(-2.5,0.5) R14(-1.5,0.5) R15(-0.5,0.5) R16(0.5,0.5) R17(1.5,0.5) R18(2.5,0.5) R19(3.5,0.5) R20(4.5,0.5) R27(11.5,0.5) R28(12.5,0.5) R29(13.5,0.5) R30(14.5,0.5) T1(-14.5,-0.5) T2(-13.5,-0.5) T3(-12.5,-0.5) T4(-11.5,-0.5) T11(-4.5,-0.5) T12(-3.5,-0.5) T13(-2.5,-0.5) T14(-1.5,-0.5) T15(-0.5,-0.5) T16(0.5,-0.5) T17(1.5,-0.5) T18(2.5,-0.5) T19(3.5,-0.5) T20(4.5,-0.5) T27(11.5,-0.5) T28(12.5,-0.5) T29(13.5,-0.5) T30(14.5,-0.5) U1(-14.5,-1.5) U2(-13.5,-1.5) U3(-12.5,-1.5) U4(-11.5,-1.5) U10(-5.5,-1.5) U11(-4.5,-1.5) U12(-3.5,-1.5) U13(-2.5,-1.5) U14(-1.5,-1.5) U15(-0.5,-1.5) U16(0.5,-1.5) U17(1.5,-1.5) U18(2.5,-1.5) U19(3.5,-1.5) U20(4.5,-1.5) U21(5.5,-1.5) U27(11.5,-1.5) U28(12.5,-1.5) U29(13.5,-1.5) U30(14.5,-1.5) V1(-14.5,-2.5) V2(-13.5,-2.5) V3(-12.5,-2.5) V4(-11.5,-2.5) V10(-5.5,-2.5) V11(-4.5,-2.5) V12(-3.5,-2.5) V13(-2.5,-2.5) V14(-1.5,-2.5) V15(-0.5,-2.5) V16(0.5,-2.5) V17(1.5,-2.5) V18(2.5,-2.5) V19(3.5,-2.5) V20(4.5,-2.5) V21(5.5,-2.5) V27(11.5,-2.5) V28(12.5,-2.5) V29(13.5,-2.5) V30(14.5,-2.5) W1(-14.5,-3.5) W2(-13.5,-3.5) W3(-12.5,-3.5) W4(-11.5,-3.5) W10(-5.5,-3.5) W11(-4.5,-3.5) W12(-3.5,-3.5) W13(-2.5,-3.5) W14(-1.5,-3.5) W15(-0.5,-3.5) W16(0.5,-3.5) W17(1.5,-3.5) W18(2.5,-3.5) W19(3.5,-3.5) W20(4.5,-3.5) W21(5.5,-3.5) W27(11.5,-3.5) W28(12.5,-3.5) W29(13.5,-3.5) W30(14.5,-3.5) Y1(-14.5,-4.5) Y2(-13.5,-4.5) Y3(-12.5,-4.5) Y4(-11.5,-4.5) Y10(-5.5,-4.5) Y11(-4.5,-4.5) Y12(-3.5,-4.5) Y13(-2.5,-4.5) Y14(-1.5,-4.5) Y15(-0.5,-4.5) Y16(0.5,-4.5) Y17(1.5,-4.5) Y18(2.5,-4.5) Y19(3.5,-4.5) Y20(4.5,-4.5) Y21(5.5,-4.5) Y27(11.5,-4.5) Y28(12.5,-4.5) Y29(13.5,-4.5) Y30(14.5,-4.5)
Top Overlay:
  circle w0.25: c-16.15,14.5 r0.125
  region: -14.5,15.5 -15.5,14.5 -15.5,15.5
  lines w0.2: -15.5,14.5 -14.5,15.5 ; -15.5,-15.5 -15.5,15.5 15.5,15.5 15.5,-15.5 -15.5,-15.5
Mechanical 13:
  lines w0.1: -15.5,-15.5 -15.5,15.5 15.5,15.5 15.5,-15.5 -15.5,-15.5
Mechanical 15:
  lines w0.1: -0.5,0 0.5,0 ; 0,-0.5 0,0.5 ; -16.5,-16.5 -16.5,16.5 16.5,16.5 16.5,-16.5 -16.5,-16.5
3D body: height 2.6, standoff 0, extent -15.5,-15.5 15.5,15.5

## FG676 [mm] "676-Ball Fine Pitch Ball Grid Array (FG676)"
height 2.6
pads (676):
  round 0.5 smd: A1(-12.5,12.5) A2(-11.5,12.5) A3(-10.5,12.5) A4(-9.5,12.5) A5(-8.5,12.5) A6(-7.5,12.5) A7(-6.5,12.5) A8(-5.5,12.5) A9(-4.5,12.5) A10(-3.5,12.5) A11(-2.5,12.5) A12(-1.5,12.5) A13(-0.5,12.5) A14(0.5,12.5) A15(1.5,12.5) A16(2.5,12.5) A17(3.5,12.5) A18(4.5,12.5) A19(5.5,12.5) A20(6.5,12.5) A21(7.5,12.5) A22(8.5,12.5) A23(9.5,12.5) A24(10.5,12.5) A25(11.5,12.5) A26(12.5,12.5) AA1(-12.5,-7.5) AA2(-11.5,-7.5) AA3(-10.5,-7.5) AA4(-9.5,-7.5) AA5(-8.5,-7.5) AA6(-7.5,-7.5) AA7(-6.5,-7.5) AA8(-5.5,-7.5) AA9(-4.5,-7.5) AA10(-3.5,-7.5) AA11(-2.5,-7.5) AA12(-1.5,-7.5) AA13(-0.5,-7.5) AA14(0.5,-7.5) AA15(1.5,-7.5) AA16(2.5,-7.5) AA17(3.5,-7.5) AA18(4.5,-7.5) AA19(5.5,-7.5) AA20(6.5,-7.5) AA21(7.5,-7.5) AA22(8.5,-7.5) AA23(9.5,-7.5) AA24(10.5,-7.5) AA25(11.5,-7.5) AA26(12.5,-7.5) AB1(-12.5,-8.5) AB2(-11.5,-8.5) AB3(-10.5,-8.5) AB4(-9.5,-8.5) AB5(-8.5,-8.5) AB6(-7.5,-8.5) AB7(-6.5,-8.5) AB8(-5.5,-8.5) AB9(-4.5,-8.5) AB10(-3.5,-8.5) AB11(-2.5,-8.5) AB12(-1.5,-8.5) AB13(-0.5,-8.5) AB14(0.5,-8.5) AB15(1.5,-8.5) AB16(2.5,-8.5) AB17(3.5,-8.5) AB18(4.5,-8.5) AB19(5.5,-8.5) AB20(6.5,-8.5) AB21(7.5,-8.5) AB22(8.5,-8.5) AB23(9.5,-8.5) AB24(10.5,-8.5) AB25(11.5,-8.5) AB26(12.5,-8.5) AC1(-12.5,-9.5) AC2(-11.5,-9.5) AC3(-10.5,-9.5) AC4(-9.5,-9.5) AC5(-8.5,-9.5) AC6(-7.5,-9.5) AC7(-6.5,-9.5) AC8(-5.5,-9.5) AC9(-4.5,-9.5) AC10(-3.5,-9.5) AC11(-2.5,-9.5) AC12(-1.5,-9.5) AC13(-0.5,-9.5) AC14(0.5,-9.5) AC15(1.5,-9.5) AC16(2.5,-9.5) AC17(3.5,-9.5) AC18(4.5,-9.5) AC19(5.5,-9.5) AC20(6.5,-9.5) AC21(7.5,-9.5) AC22(8.5,-9.5) AC23(9.5,-9.5) AC24(10.5,-9.5) AC25(11.5,-9.5) AC26(12.5,-9.5) AD1(-12.5,-10.5) AD2(-11.5,-10.5) AD3(-10.5,-10.5) AD4(-9.5,-10.5) AD5(-8.5,-10.5) AD6(-7.5,-10.5) AD7(-6.5,-10.5) AD8(-5.5,-10.5) AD9(-4.5,-10.5) AD10(-3.5,-10.5) AD11(-2.5,-10.5) AD12(-1.5,-10.5) AD13(-0.5,-10.5) AD14(0.5,-10.5) AD15(1.5,-10.5) AD16(2.5,-10.5) AD17(3.5,-10.5) AD18(4.5,-10.5) AD19(5.5,-10.5) AD20(6.5,-10.5) AD21(7.5,-10.5) AD22(8.5,-10.5) AD23(9.5,-10.5) AD24(10.5,-10.5) AD25(11.5,-10.5) AD26(12.5,-10.5) AE1(-12.5,-11.5) AE2(-11.5,-11.5) AE3(-10.5,-11.5) AE4(-9.5,-11.5) AE5(-8.5,-11.5) AE6(-7.5,-11.5) AE7(-6.5,-11.5) AE8(-5.5,-11.5) AE9(-4.5,-11.5) AE10(-3.5,-11.5) AE11(-2.5,-11.5) AE12(-1.5,-11.5) AE13(-0.5,-11.5) AE14(0.5,-11.5) AE15(1.5,-11.5) AE16(2.5,-11.5) AE17(3.5,-11.5) AE18(4.5,-11.5) AE19(5.5,-11.5) AE20(6.5,-11.5) AE21(7.5,-11.5) AE22(8.5,-11.5) AE23(9.5,-11.5) AE24(10.5,-11.5) AE25(11.5,-11.5) AE26(12.5,-11.5) AF1(-12.5,-12.5) AF2(-11.5,-12.5) AF3(-10.5,-12.5) AF4(-9.5,-12.5) AF5(-8.5,-12.5) AF6(-7.5,-12.5) AF7(-6.5,-12.5) AF8(-5.5,-12.5) AF9(-4.5,-12.5) AF10(-3.5,-12.5) AF11(-2.5,-12.5) AF12(-1.5,-12.5) AF13(-0.5,-12.5) AF14(0.5,-12.5) AF15(1.5,-12.5) AF16(2.5,-12.5) AF17(3.5,-12.5) AF18(4.5,-12.5) AF19(5.5,-12.5) AF20(6.5,-12.5) AF21(7.5,-12.5) AF22(8.5,-12.5) AF23(9.5,-12.5) AF24(10.5,-12.5) AF25(11.5,-12.5) AF26(12.5,-12.5) B1(-12.5,11.5) B2(-11.5,11.5) B3(-10.5,11.5) B4(-9.5,11.5) B5(-8.5,11.5) B6(-7.5,11.5) B7(-6.5,11.5) B8(-5.5,11.5) B9(-4.5,11.5) B10(-3.5,11.5) B11(-2.5,11.5) B12(-1.5,11.5) B13(-0.5,11.5) B14(0.5,11.5) B15(1.5,11.5) B16(2.5,11.5) B17(3.5,11.5) B18(4.5,11.5) B19(5.5,11.5) B20(6.5,11.5) B21(7.5,11.5) B22(8.5,11.5) B23(9.5,11.5) B24(10.5,11.5) B25(11.5,11.5) B26(12.5,11.5) C1(-12.5,10.5) C2(-11.5,10.5) C3(-10.5,10.5) C4(-9.5,10.5) C5(-8.5,10.5) C6(-7.5,10.5) C7(-6.5,10.5) C8(-5.5,10.5) C9(-4.5,10.5) C10(-3.5,10.5) C11(-2.5,10.5) C12(-1.5,10.5) C13(-0.5,10.5) C14(0.5,10.5) C15(1.5,10.5) C16(2.5,10.5) C17(3.5,10.5) C18(4.5,10.5) C19(5.5,10.5) C20(6.5,10.5) C21(7.5,10.5) C22(8.5,10.5) C23(9.5,10.5) C24(10.5,10.5) C25(11.5,10.5) C26(12.5,10.5) D1(-12.5,9.5) D2(-11.5,9.5) D3(-10.5,9.5) D4(-9.5,9.5) D5(-8.5,9.5) D6(-7.5,9.5) D7(-6.5,9.5) D8(-5.5,9.5) D9(-4.5,9.5) D10(-3.5,9.5) D11(-2.5,9.5) D12(-1.5,9.5) D13(-0.5,9.5) D14(0.5,9.5) D15(1.5,9.5) D16(2.5,9.5) D17(3.5,9.5) D18(4.5,9.5) D19(5.5,9.5) D20(6.5,9.5) D21(7.5,9.5) D22(8.5,9.5) D23(9.5,9.5) D24(10.5,9.5) D25(11.5,9.5) D26(12.5,9.5) E1(-12.5,8.5) E2(-11.5,8.5) E3(-10.5,8.5) E4(-9.5,8.5) E5(-8.5,8.5) E6(-7.5,8.5) E7(-6.5,8.5) E8(-5.5,8.5) E9(-4.5,8.5) E10(-3.5,8.5) E11(-2.5,8.5) E12(-1.5,8.5) E13(-0.5,8.5) E14(0.5,8.5) E15(1.5,8.5) E16(2.5,8.5) E17(3.5,8.5) E18(4.5,8.5) E19(5.5,8.5) E20(6.5,8.5) E21(7.5,8.5) E22(8.5,8.5) E23(9.5,8.5) E24(10.5,8.5) E25(11.5,8.5) E26(12.5,8.5) F1(-12.5,7.5) F2(-11.5,7.5) F3(-10.5,7.5) F4(-9.5,7.5) F5(-8.5,7.5) F6(-7.5,7.5) F7(-6.5,7.5) F8(-5.5,7.5) F9(-4.5,7.5) F10(-3.5,7.5) F11(-2.5,7.5) F12(-1.5,7.5) F13(-0.5,7.5) F14(0.5,7.5) F15(1.5,7.5) F16(2.5,7.5) F17(3.5,7.5) F18(4.5,7.5) F19(5.5,7.5) F20(6.5,7.5) F21(7.5,7.5) F22(8.5,7.5) F23(9.5,7.5) F24(10.5,7.5) F25(11.5,7.5) F26(12.5,7.5) G1(-12.5,6.5) G2(-11.5,6.5) G3(-10.5,6.5) G4(-9.5,6.5) G5(-8.5,6.5) G6(-7.5,6.5) G7(-6.5,6.5) G8(-5.5,6.5) G9(-4.5,6.5) G10(-3.5,6.5) G11(-2.5,6.5) G12(-1.5,6.5) G13(-0.5,6.5) G14(0.5,6.5) G15(1.5,6.5) G16(2.5,6.5) G17(3.5,6.5) G18(4.5,6.5) G19(5.5,6.5) G20(6.5,6.5) G21(7.5,6.5) G22(8.5,6.5) G23(9.5,6.5) G24(10.5,6.5) G25(11.5,6.5) G26(12.5,6.5) H1(-12.5,5.5) H2(-11.5,5.5) H3(-10.5,5.5) H4(-9.5,5.5) H5(-8.5,5.5) H6(-7.5,5.5) H7(-6.5,5.5) H8(-5.5,5.5) H9(-4.5,5.5) H10(-3.5,5.5) H11(-2.5,5.5) H12(-1.5,5.5) H13(-0.5,5.5) H14(0.5,5.5) H15(1.5,5.5) H16(2.5,5.5) H17(3.5,5.5) H18(4.5,5.5) H19(5.5,5.5) H20(6.5,5.5) H21(7.5,5.5) H22(8.5,5.5) H23(9.5,5.5) H24(10.5,5.5) H25(11.5,5.5) H26(12.5,5.5) J1(-12.5,4.5) J2(-11.5,4.5) J3(-10.5,4.5) J4(-9.5,4.5) J5(-8.5,4.5) J6(-7.5,4.5) J7(-6.5,4.5) J8(-5.5,4.5) J9(-4.5,4.5) J10(-3.5,4.5) J11(-2.5,4.5) J12(-1.5,4.5) J13(-0.5,4.5) J14(0.5,4.5) J15(1.5,4.5) J16(2.5,4.5) J17(3.5,4.5) J18(4.5,4.5) J19(5.5,4.5) J20(6.5,4.5) J21(7.5,4.5) J22(8.5,4.5) J23(9.5,4.5) J24(10.5,4.5) J25(11.5,4.5) J26(12.5,4.5) K1(-12.5,3.5) K2(-11.5,3.5) K3(-10.5,3.5) K4(-9.5,3.5) K5(-8.5,3.5) K6(-7.5,3.5) K7(-6.5,3.5) K8(-5.5,3.5) K9(-4.5,3.5) K10(-3.5,3.5) K11(-2.5,3.5) K12(-1.5,3.5) K13(-0.5,3.5) K14(0.5,3.5) K15(1.5,3.5) K16(2.5,3.5) K17(3.5,3.5) K18(4.5,3.5) K19(5.5,3.5) K20(6.5,3.5) K21(7.5,3.5) K22(8.5,3.5) K23(9.5,3.5) K24(10.5,3.5) K25(11.5,3.5) K26(12.5,3.5) L1(-12.5,2.5) L2(-11.5,2.5) L3(-10.5,2.5) L4(-9.5,2.5) L5(-8.5,2.5) L6(-7.5,2.5) L7(-6.5,2.5) L8(-5.5,2.5) L9(-4.5,2.5) L10(-3.5,2.5) L11(-2.5,2.5) L12(-1.5,2.5) L13(-0.5,2.5) L14(0.5,2.5) L15(1.5,2.5) L16(2.5,2.5) L17(3.5,2.5) L18(4.5,2.5) L19(5.5,2.5) L20(6.5,2.5) L21(7.5,2.5) L22(8.5,2.5) L23(9.5,2.5) L24(10.5,2.5) L25(11.5,2.5) L26(12.5,2.5) M1(-12.5,1.5) M2(-11.5,1.5) M3(-10.5,1.5) M4(-9.5,1.5) M5(-8.5,1.5) M6(-7.5,1.5) M7(-6.5,1.5) M8(-5.5,1.5) M9(-4.5,1.5) M10(-3.5,1.5) M11(-2.5,1.5) M12(-1.5,1.5) M13(-0.5,1.5) M14(0.5,1.5) M15(1.5,1.5) M16(2.5,1.5) M17(3.5,1.5) M18(4.5,1.5) M19(5.5,1.5) M20(6.5,1.5) M21(7.5,1.5) M22(8.5,1.5) M23(9.5,1.5) M24(10.5,1.5) M25(11.5,1.5) M26(12.5,1.5) N1(-12.5,0.5) N2(-11.5,0.5) N3(-10.5,0.5) N4(-9.5,0.5) N5(-8.5,0.5) N6(-7.5,0.5) N7(-6.5,0.5) N8(-5.5,0.5) N9(-4.5,0.5) N10(-3.5,0.5) N11(-2.5,0.5) N12(-1.5,0.5) N13(-0.5,0.5) N14(0.5,0.5) N15(1.5,0.5) N16(2.5,0.5) N17(3.5,0.5) N18(4.5,0.5) N19(5.5,0.5) N20(6.5,0.5) N21(7.5,0.5) N22(8.5,0.5) N23(9.5,0.5) N24(10.5,0.5) N25(11.5,0.5) N26(12.5,0.5) P1(-12.5,-0.5) P2(-11.5,-0.5) P3(-10.5,-0.5) P4(-9.5,-0.5) P5(-8.5,-0.5) P6(-7.5,-0.5) P7(-6.5,-0.5) P8(-5.5,-0.5) P9(-4.5,-0.5) P10(-3.5,-0.5) P11(-2.5,-0.5) P12(-1.5,-0.5) P13(-0.5,-0.5) P14(0.5,-0.5) P15(1.5,-0.5) P16(2.5,-0.5) P17(3.5,-0.5) P18(4.5,-0.5) P19(5.5,-0.5) P20(6.5,-0.5) P21(7.5,-0.5) P22(8.5,-0.5) P23(9.5,-0.5) P24(10.5,-0.5) P25(11.5,-0.5) P26(12.5,-0.5) R1(-12.5,-1.5) R2(-11.5,-1.5) R3(-10.5,-1.5) R4(-9.5,-1.5) R5(-8.5,-1.5) R6(-7.5,-1.5) R7(-6.5,-1.5) R8(-5.5,-1.5) R9(-4.5,-1.5) R10(-3.5,-1.5) R11(-2.5,-1.5) R12(-1.5,-1.5) R13(-0.5,-1.5) R14(0.5,-1.5) R15(1.5,-1.5) R16(2.5,-1.5) R17(3.5,-1.5) R18(4.5,-1.5) R19(5.5,-1.5) R20(6.5,-1.5) R21(7.5,-1.5) R22(8.5,-1.5) R23(9.5,-1.5) R24(10.5,-1.5) R25(11.5,-1.5) R26(12.5,-1.5) T1(-12.5,-2.5) T2(-11.5,-2.5) T3(-10.5,-2.5) T4(-9.5,-2.5) T5(-8.5,-2.5) T6(-7.5,-2.5) T7(-6.5,-2.5) T8(-5.5,-2.5) T9(-4.5,-2.5) T10(-3.5,-2.5) T11(-2.5,-2.5) T12(-1.5,-2.5) T13(-0.5,-2.5) T14(0.5,-2.5) T15(1.5,-2.5) T16(2.5,-2.5) T17(3.5,-2.5) T18(4.5,-2.5) T19(5.5,-2.5) T20(6.5,-2.5) T21(7.5,-2.5) T22(8.5,-2.5) T23(9.5,-2.5) T24(10.5,-2.5) T25(11.5,-2.5) T26(12.5,-2.5) U1(-12.5,-3.5) U2(-11.5,-3.5) U3(-10.5,-3.5) U4(-9.5,-3.5) U5(-8.5,-3.5) U6(-7.5,-3.5) U7(-6.5,-3.5) U8(-5.5,-3.5) U9(-4.5,-3.5) U10(-3.5,-3.5) U11(-2.5,-3.5) U12(-1.5,-3.5) U13(-0.5,-3.5) U14(0.5,-3.5) U15(1.5,-3.5) U16(2.5,-3.5) U17(3.5,-3.5) U18(4.5,-3.5) U19(5.5,-3.5) U20(6.5,-3.5) U21(7.5,-3.5) U22(8.5,-3.5) U23(9.5,-3.5) U24(10.5,-3.5) U25(11.5,-3.5) U26(12.5,-3.5) V1(-12.5,-4.5) V2(-11.5,-4.5) V3(-10.5,-4.5) V4(-9.5,-4.5) V5(-8.5,-4.5) V6(-7.5,-4.5) V7(-6.5,-4.5) V8(-5.5,-4.5) V9(-4.5,-4.5) V10(-3.5,-4.5) V11(-2.5,-4.5) V12(-1.5,-4.5) V13(-0.5,-4.5) V14(0.5,-4.5) V15(1.5,-4.5) V16(2.5,-4.5) V17(3.5,-4.5) V18(4.5,-4.5) V19(5.5,-4.5) V20(6.5,-4.5) V21(7.5,-4.5) V22(8.5,-4.5) V23(9.5,-4.5) V24(10.5,-4.5) V25(11.5,-4.5) V26(12.5,-4.5) W1(-12.5,-5.5) W2(-11.5,-5.5) W3(-10.5,-5.5) W4(-9.5,-5.5) W5(-8.5,-5.5) W6(-7.5,-5.5) W7(-6.5,-5.5) W8(-5.5,-5.5) W9(-4.5,-5.5) W10(-3.5,-5.5) W11(-2.5,-5.5) W12(-1.5,-5.5) W13(-0.5,-5.5) W14(0.5,-5.5) W15(1.5,-5.5) W16(2.5,-5.5) W17(3.5,-5.5) W18(4.5,-5.5) W19(5.5,-5.5) W20(6.5,-5.5) W21(7.5,-5.5) W22(8.5,-5.5) W23(9.5,-5.5) W24(10.5,-5.5) W25(11.5,-5.5) W26(12.5,-5.5) Y1(-12.5,-6.5) Y2(-11.5,-6.5) Y3(-10.5,-6.5) Y4(-9.5,-6.5) Y5(-8.5,-6.5) Y6(-7.5,-6.5) Y7(-6.5,-6.5) Y8(-5.5,-6.5) Y9(-4.5,-6.5) Y10(-3.5,-6.5) Y11(-2.5,-6.5) Y12(-1.5,-6.5) Y13(-0.5,-6.5) Y14(0.5,-6.5) Y15(1.5,-6.5) Y16(2.5,-6.5) Y17(3.5,-6.5) Y18(4.5,-6.5) Y19(5.5,-6.5) Y20(6.5,-6.5) Y21(7.5,-6.5) Y22(8.5,-6.5) Y23(9.5,-6.5) Y24(10.5,-6.5) Y25(11.5,-6.5) Y26(12.5,-6.5)
Top Overlay:
  circle w0.25: c-14.15,12.5 r0.125
  region: -12.5,13.5 -13.5,12.5 -13.5,13.5
  lines w0.2: -13.5,12.5 -12.5,13.5 ; -13.5,-13.5 13.5,-13.5 13.5,13.5 -13.5,13.5 -13.5,-13.5
Mechanical 13:
  lines w0.1: -13.5,-13.5 13.5,-13.5 13.5,13.5 -13.5,13.5 -13.5,-13.5
Mechanical 15:
  lines w0.1: -0.5,0 0.5,0 ; 0,-0.5 0,0.5 ; -14.5,-14.5 14.5,-14.5 14.5,14.5 -14.5,14.5 -14.5,-14.5
3D body: height 2.6, standoff 0, extent -13.5,-13.5 13.5,13.5

## FG680 [mm] "680-Ball Fine Pitch Ball Grid Array (FG680)"
height 1.7
pads (680):
  round 0.5 smd: A1(-19,19) A2(-18,19) A3(-17,19) A4(-16,19) A5(-15,19) A6(-14,19) A7(-13,19) A8(-12,19) A9(-11,19) A10(-10,19) A11(-9,19) A12(-8,19) A13(-7,19) A14(-6,19) A15(-5,19) A16(-4,19) A17(-3,19) A18(-2,19) A19(-1,19) A20(0,19) A21(1,19) A22(2,19) A23(3,19) A24(4,19) A25(5,19) A26(6,19) A27(7,19) A28(8,19) A29(9,19) A30(10,19) A31(11,19) A32(12,19) A33(13,19) A34(14,19) A35(15,19) A36(16,19) A37(17,19) A38(18,19) A39(19,19) AA1(-19,-1) AA2(-18,-1) AA3(-17,-1) AA4(-16,-1) AA5(-15,-1) AA35(15,-1) AA36(16,-1) AA37(17,-1) AA38(18,-1) AA39(19,-1) AB1(-19,-2) AB2(-18,-2) AB3(-17,-2) AB4(-16,-2) AB5(-15,-2) AB35(15,-2) AB36(16,-2) AB37(17,-2) AB38(18,-2) AB39(19,-2) AC1(-19,-3) AC2(-18,-3) AC3(-17,-3) AC4(-16,-3) AC5(-15,-3) AC35(15,-3) AC36(16,-3) AC37(17,-3) AC38(18,-3) AC39(19,-3) AD1(-19,-4) AD2(-18,-4) AD3(-17,-4) AD4(-16,-4) AD5(-15,-4) AD35(15,-4) AD36(16,-4) AD37(17,-4) AD38(18,-4) AD39(19,-4) AE1(-19,-5) AE2(-18,-5) AE3(-17,-5) AE4(-16,-5) AE5(-15,-5) AE35(15,-5) AE36(16,-5) AE37(17,-5) AE38(18,-5) AE39(19,-5) AF1(-19,-6) AF2(-18,-6) AF3(-17,-6) AF4(-16,-6) AF5(-15,-6) AF35(15,-6) AF36(16,-6) AF37(17,-6) AF38(18,-6) AF39(19,-6) AG1(-19,-7) AG2(-18,-7) AG3(-17,-7) AG4(-16,-7) AG5(-15,-7) AG35(15,-7) AG36(16,-7) AG37(17,-7) AG38(18,-7) AG39(19,-7) AH1(-19,-8) AH2(-18,-8) AH3(-17,-8) AH4(-16,-8) AH5(-15,-8) AH35(15,-8) AH36(16,-8) AH37(17,-8) AH38(18,-8) AH39(19,-8) AJ1(-19,-9) AJ2(-18,-9) AJ3(-17,-9) AJ4(-16,-9) AJ5(-15,-9) AJ35(15,-9) AJ36(16,-9) AJ37(17,-9) AJ38(18,-9) AJ39(19,-9) AK1(-19,-10) AK2(-18,-10) AK3(-17,-10) AK4(-16,-10) AK5(-15,-10) AK35(15,-10) AK36(16,-10) AK37(17,-10) AK38(18,-10) AK39(19,-10) AL1(-19,-11) AL2(-18,-11) AL3(-17,-11) AL4(-16,-11) AL5(-15,-11) AL35(15,-11) AL36(16,-11) AL37(17,-11) AL38(18,-11) AL39(19,-11) AM1(-19,-12) AM2(-18,-12) AM3(-17,-12) AM4(-16,-12) AM5(-15,-12) AM35(15,-12) AM36(16,-12) AM37(17,-12) AM38(18,-12) AM39(19,-12) AN1(-19,-13) AN2(-18,-13) AN3(-17,-13) AN4(-16,-13) AN5(-15,-13) AN35(15,-13) AN36(16,-13) AN37(17,-13) AN38(18,-13) AN39(19,-13) AP1(-19,-14) AP2(-18,-14) AP3(-17,-14) AP4(-16,-14) AP5(-15,-14) AP35(15,-14) AP36(16,-14) AP37(17,-14) AP38(18,-14) AP39(19,-14) AR1(-19,-15) AR2(-18,-15) AR3(-17,-15) AR4(-16,-15) AR5(-15,-15) AR6(-14,-15) AR7(-13,-15) AR8(-12,-15) AR9(-11,-15) AR10(-10,-15) AR11(-9,-15) AR12(-8,-15) AR13(-7,-15) AR14(-6,-15) AR15(-5,-15) AR16(-4,-15) AR17(-3,-15) AR18(-2,-15) AR19(-1,-15) AR20(0,-15) AR21(1,-15) AR22(2,-15) AR23(3,-15) AR24(4,-15) AR25(5,-15) AR26(6,-15) AR27(7,-15) AR28(8,-15) AR29(9,-15) AR30(10,-15) AR31(11,-15) AR32(12,-15) AR33(13,-15) AR34(14,-15) AR35(15,-15) AR36(16,-15) AR37(17,-15) AR38(18,-15) AR39(19,-15) AT1(-19,-16) AT2(-18,-16) AT3(-17,-16) AT4(-16,-16) AT5(-15,-16) AT6(-14,-16) AT7(-13,-16) AT8(-12,-16) AT9(-11,-16) AT10(-10,-16) AT11(-9,-16) AT12(-8,-16) AT13(-7,-16) AT14(-6,-16) AT15(-5,-16) AT16(-4,-16) AT17(-3,-16) AT18(-2,-16) AT19(-1,-16) AT20(0,-16) AT21(1,-16) AT22(2,-16) AT23(3,-16) AT24(4,-16) AT25(5,-16) AT26(6,-16) AT27(7,-16) AT28(8,-16) AT29(9,-16) AT30(10,-16) AT31(11,-16) AT32(12,-16) AT33(13,-16) AT34(14,-16) AT35(15,-16) AT36(16,-16) AT37(17,-16) AT38(18,-16) AT39(19,-16) AU1(-19,-17) AU2(-18,-17) AU3(-17,-17) AU4(-16,-17) AU5(-15,-17) AU6(-14,-17) AU7(-13,-17) AU8(-12,-17) AU9(-11,-17) AU10(-10,-17) AU11(-9,-17) AU12(-8,-17) AU13(-7,-17) AU14(-6,-17) AU15(-5,-17) AU16(-4,-17) AU17(-3,-17) AU18(-2,-17) AU19(-1,-17) AU20(0,-17) AU21(1,-17) AU22(2,-17) AU23(3,-17) AU24(4,-17) AU25(5,-17) AU26(6,-17) AU27(7,-17) AU28(8,-17) AU29(9,-17) AU30(10,-17) AU31(11,-17) AU32(12,-17) AU33(13,-17) AU34(14,-17) AU35(15,-17) AU36(16,-17) AU37(17,-17) AU38(18,-17) AU39(19,-17) AV1(-19,-18) AV2(-18,-18) AV3(-17,-18) AV4(-16,-18) AV5(-15,-18) AV6(-14,-18) AV7(-13,-18) AV8(-12,-18) AV9(-11,-18) AV10(-10,-18) AV11(-9,-18) AV12(-8,-18) AV13(-7,-18) AV14(-6,-18) AV15(-5,-18) AV16(-4,-18) AV17(-3,-18) AV18(-2,-18) AV19(-1,-18) AV20(0,-18) AV21(1,-18) AV22(2,-18) AV23(3,-18) AV24(4,-18) AV25(5,-18) AV26(6,-18) AV27(7,-18) AV28(8,-18) AV29(9,-18) AV30(10,-18) AV31(11,-18) AV32(12,-18) AV33(13,-18) AV34(14,-18) AV35(15,-18) AV36(16,-18) AV37(17,-18) AV38(18,-18) AV39(19,-18) AW1(-19,-19) AW2(-18,-19) AW3(-17,-19) AW4(-16,-19) AW5(-15,-19) AW6(-14,-19) AW7(-13,-19) AW8(-12,-19) AW9(-11,-19) AW10(-10,-19) AW11(-9,-19) AW12(-8,-19) AW13(-7,-19) AW14(-6,-19) AW15(-5,-19) AW16(-4,-19) AW17(-3,-19) AW18(-2,-19) AW19(-1,-19) AW20(0,-19) AW21(1,-19) AW22(2,-19) AW23(3,-19) AW24(4,-19) AW25(5,-19) AW26(6,-19) AW27(7,-19) AW28(8,-19) AW29(9,-19) AW30(10,-19) AW31(11,-19) AW32(12,-19) AW33(13,-19) AW34(14,-19) AW35(15,-19) AW36(16,-19) AW37(17,-19) AW38(18,-19) AW39(19,-19) B1(-19,18) B2(-18,18) B3(-17,18) B4(-16,18) B5(-15,18) B6(-14,18) B7(-13,18) B8(-12,18) B9(-11,18) B10(-10,18) B11(-9,18) B12(-8,18) B13(-7,18) B14(-6,18) B15(-5,18) B16(-4,18) B17(-3,18) B18(-2,18) B19(-1,18) B20(0,18) B21(1,18) B22(2,18) B23(3,18) B24(4,18) B25(5,18) B26(6,18) B27(7,18) B28(8,18) B29(9,18) B30(10,18) B31(11,18) B32(12,18) B33(13,18) B34(14,18) B35(15,18) B36(16,18) B37(17,18) B38(18,18) B39(19,18) C1(-19,17) C2(-18,17) C3(-17,17) C4(-16,17) C5(-15,17) C6(-14,17) C7(-13,17) C8(-12,17) C9(-11,17) C10(-10,17) C11(-9,17) C12(-8,17) C13(-7,17) C14(-6,17) C15(-5,17) C16(-4,17) C17(-3,17) C18(-2,17) C19(-1,17) C20(0,17) C21(1,17) C22(2,17) C23(3,17) C24(4,17) C25(5,17) C26(6,17) C27(7,17) C28(8,17) C29(9,17) C30(10,17) C31(11,17) C32(12,17) C33(13,17) C34(14,17) C35(15,17) C36(16,17) C37(17,17) C38(18,17) C39(19,17) D1(-19,16) D2(-18,16) D3(-17,16) D4(-16,16) D5(-15,16) D6(-14,16) D7(-13,16) D8(-12,16) D9(-11,16) D10(-10,16) D11(-9,16) D12(-8,16) D13(-7,16) D14(-6,16) D15(-5,16) D16(-4,16) D17(-3,16) D18(-2,16) D19(-1,16) D20(0,16) D21(1,16) D22(2,16) D23(3,16) D24(4,16) D25(5,16) D26(6,16) D27(7,16) D28(8,16) D29(9,16) D30(10,16) D31(11,16) D32(12,16) D33(13,16) D34(14,16) D35(15,16) D36(16,16) D37(17,16) D38(18,16) D39(19,16) E1(-19,15) E2(-18,15) E3(-17,15) E4(-16,15) E5(-15,15) E6(-14,15) E7(-13,15) E8(-12,15) E9(-11,15) E10(-10,15) E11(-9,15) E12(-8,15) E13(-7,15) E14(-6,15) E15(-5,15) E16(-4,15) E17(-3,15) E18(-2,15) E19(-1,15) E20(0,15) E21(1,15) E22(2,15) E23(3,15) E24(4,15) E25(5,15) E26(6,15) E27(7,15) E28(8,15) E29(9,15) E30(10,15) E31(11,15) E32(12,15) E33(13,15) E34(14,15) E35(15,15) E36(16,15) E37(17,15) E38(18,15) E39(19,15) F1(-19,14) F2(-18,14) F3(-17,14) F4(-16,14) F5(-15,14) F35(15,14) F36(16,14) F37(17,14) F38(18,14) F39(19,14) G1(-19,13) G2(-18,13) G3(-17,13) G4(-16,13) G5(-15,13) G35(15,13) G36(16,13) G37(17,13) G38(18,13) G39(19,13) H1(-19,12) H2(-18,12) H3(-17,12) H4(-16,12) H5(-15,12) H35(15,12) H36(16,12) H37(17,12) H38(18,12) H39(19,12) J1(-19,11) J2(-18,11) J3(-17,11) J4(-16,11) J5(-15,11) J35(15,11) J36(16,11) J37(17,11) J38(18,11) J39(19,11) K1(-19,10) K2(-18,10) K3(-17,10) K4(-16,10) K5(-15,10) K35(15,10) K36(16,10) K37(17,10) K38(18,10) K39(19,10) L1(-19,9) L2(-18,9) L3(-17,9) L4(-16,9) L5(-15,9) L35(15,9) L36(16,9) L37(17,9) L38(18,9) L39(19,9) M1(-19,8) M2(-18,8) M3(-17,8) M4(-16,8) M5(-15,8) M35(15,8) M36(16,8) M37(17,8) M38(18,8) M39(19,8) N1(-19,7) N2(-18,7) N3(-17,7) N4(-16,7) N5(-15,7) N35(15,7) N36(16,7) N37(17,7) N38(18,7) N39(19,7) P1(-19,6) P2(-18,6) P3(-17,6) P4(-16,6) P5(-15,6) P35(15,6) P36(16,6) P37(17,6) P38(18,6) P39(19,6) R1(-19,5) R2(-18,5) R3(-17,5) R4(-16,5) R5(-15,5) R35(15,5) R36(16,5) R37(17,5) R38(18,5) R39(19,5) T1(-19,4) T2(-18,4) T3(-17,4) T4(-16,4) T5(-15,4) T35(15,4) T36(16,4) T37(17,4) T38(18,4) T39(19,4) U1(-19,3) U2(-18,3) U3(-17,3) U4(-16,3) U5(-15,3) U35(15,3) U36(16,3) U37(17,3) U38(18,3) U39(19,3) V1(-19,2) V2(-18,2) V3(-17,2) V4(-16,2) V5(-15,2) V35(15,2) V36(16,2) V37(17,2) V38(18,2) V39(19,2) W1(-19,1) W2(-18,1) W3(-17,1) W4(-16,1) W5(-15,1) W35(15,1) W36(16,1) W37(17,1) W38(18,1) W39(19,1) Y1(-19,0) Y2(-18,0) Y3(-17,0) Y4(-16,0) Y5(-15,0) Y35(15,0) Y36(16,0) Y37(17,0) Y38(18,0) Y39(19,0)
Top Overlay:
  circle w0.25: c-20.65,19 r0.125
  region: -19,20 -20,19 -20,20
  lines w0.2: -20,19 -19,20 ; -20,-20 20,-20 20,20 -20,20 -20,-20
Mechanical 13:
  lines w0.1: -20,-20 20,-20 20,20 -20,20 -20,-20
Mechanical 15:
  lines w0.1: -0.5,0 0.5,0 ; 0,-0.5 0,0.5 ; -21,-21 21,-21 21,21 -21,21 -21,-21
3D body: height 1.7, standoff 0, extent -20,-20 20,20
